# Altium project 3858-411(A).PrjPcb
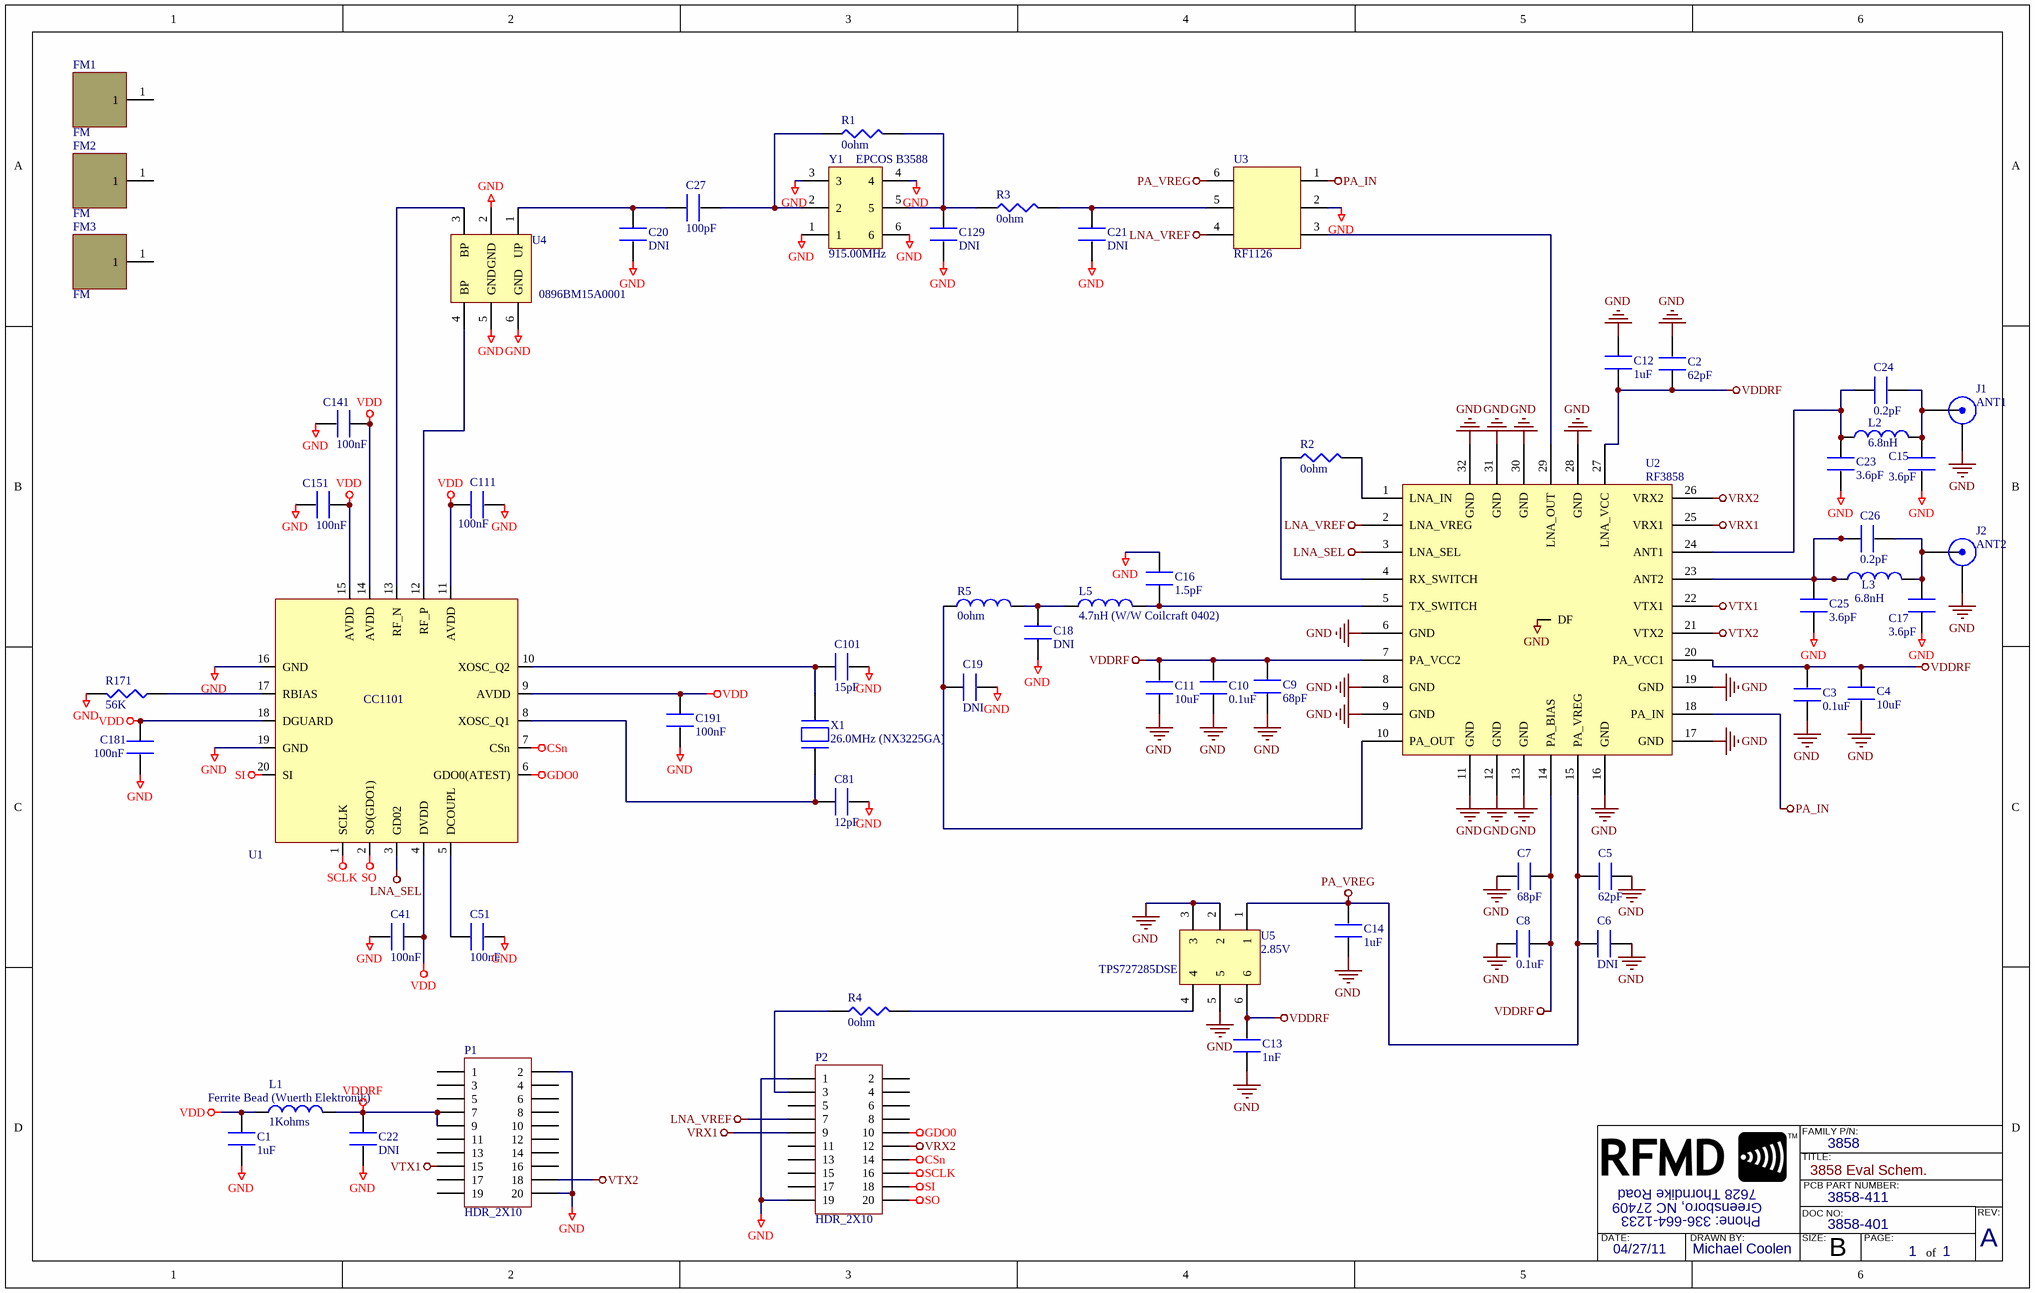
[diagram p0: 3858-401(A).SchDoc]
1 sheet, 62 parts. Net scope: global (net labels, ports and power ports of the same name join across sheets).
Board file: 3858-411(A).PcbDoc

## Sheet 3858-401(A).SchDoc: (this field not used)
size B; Organization: (this field not used); Address1: (this field not used); Address2: (this field not used); Address3: (this field not used); Address4: (this field not used); DocumentNumber: (this field not used); Revision: (this field not used); SheetNumber: (this field not used); SheetTotal: (this field not used); Date: (this field not used); ApprovedBy: (this field not used); CheckedBy: (this field not used); Author: (this field not used); CompanyName: (this field not used); DrawnBy: (this field not used); Engineer: (this field not used); AFamilypn: 3858; PageSetup: Record=PageOptions|CenterHorizontal=True|CenterVertical=True|PrintScale=1.12|XCorrection=1.00|YCorrection=1.00|PrintKind=2|BorderSize=5000000|LeftOffset=0|BottomOffset=0|Orientation=2|PaperLength=1000|PaperWidth=1000|Scale=100|PaperSource=7|PrintQuality=-4|MediaType=1|DitherType=10|PaperKind=11 x 17|PrintScaleMode=1; Apcbpartnumber: 3858-411; Atitle: 3858 Eval Schem.; Adocumentnumber: 3858-401; Apagenumber: 1; Apagenumbertotal: 1; Arevision: A; Adrawnby: Michael Coolen; Adate: 04/27/11

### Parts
C1  1uF  [0603(A)]
C2  62pF  [0402(A)]
C3  0.1uF  [0402(A)]
C4  10uF  [0603(A)]
C5  62pF  [0402(A)]
C6  DNI  [0402(A)]
C7  68pF  [0402(A)]
C8  0.1uF  [0402(A)]
C9  68pF  [0402(A)]
C10  0.1uF  [0402(A)]
C11  10uF  [0603(A)]
C12  1uF  [0402(A)]
C13  1nF  [0603(A)]
C14  1uF  [0603(A)]
C15  3.6pF  [0402_S]
C16  1.5pF  [0402_S]
C17  3.6pF  [0402_S]
C18  DNI  [0402_S]
C19  DNI  [0402_S]
C20  DNI  [0402_S]
C21  DNI  [0402_S]
C22  DNI  [0603(A)]
C23  3.6pF  [0402_S]
C24  0.2pF  [0402_S]
C25  3.6pF  [0402_S]
C26  0.2pF  [0402_S]
C27  100pF  [0402_S]
C41  100nF  [0402_TI]
C51  100nF  [0402_TI]
C81  12pF  [0402_TI]
C101  15pF  [0402_TI]
C111  100nF  [0402_TI]
C129  DNI  [0402_TI]
C141  100nF  [0402_TI]
C151  100nF  [0402_TI]
C181  100nF  [0402_TI]
C191  100nF  [0402_TI]
FM1  FM  [FM]
FM2  FM  [FM]
FM3  FM  [FM]
J1  ANT1  [SMA_008_MABDC_GP1_VIPER]
J2  ANT2  [SMA_008_MABDC_GP1_VIPER]
L1  1Kohms  [0603_S]
L2  6.8nH  [0402_S]
L3  6.8nH  [0402_S]
L5  4.7nH (W/W Coilcraft 0402)  [0402_S]
LOGO  RFMDLOGO  [RFMD_LOGO]  (value not drawn)
P1  HDR_2X10  [20PIN_CON]
P2  HDR_2X10  [20PIN_CON]
R1  0ohm  [0402_S]
R2  0ohm  [0402_S]
R3  0ohm  [0402_S]
R4  0ohm  [0402_S]
R5  0ohm  [0402_S]
R171  56K  [0402_TI]
U1  CC1101  [CC1101]
U2  RF3858  [RF3858B]
U3  RF1126  [1126]
U4  0896BM15A0001  [JOHANSON 896MHz]
U5  2.85V  [TPS727XX]
X1  26.0MHz (NX3225GA)  [Crystal]
Y1  915.00MHz  [Saw Epcos B3588]

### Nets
CSn: P2.14 U1.7(CSn)
GDO0: P2.10 U1.6(GDO0(ATEST))
GND: C1.2 C2.2 C3.1 C4.2 C5.1 C6.2 C7.2 C8.1 C9.2 C10.1 C11.1 C12.1 C13.1 C14.1 C15.2 C16.1 C17.2 C18.2 C19.2 C20.2 C21.2 C22.2 C23.2 C25.2 C41.2 C51.2 C81.2 C101.2 C111.2 C129.2 C141.2 C151.2 C181.2 C191.2 J1.2(GND) J1.3(GND) J1.4(GND) J1.5(GND) J1.6(GND) J1.7(GND) J1.8(GND) J1.9(GND) J2.2(GND) J2.3(GND) J2.4(GND) J2.5(GND) J2.6(GND) J2.7(GND) J2.8(GND) J2.9(GND) P1.2 P1.20 P2.1 P2.19 R171.2 U1.16(GND) U1.19(GND) U1.21(GND) U2.6(GND) U2.8(GND) U2.9(GND) U2.11(GND) U2.12(GND) U2.13(GND) U2.16(GND) U2.17(GND) U2.19(GND) U2.28(GND) U2.30(GND) U2.31(GND) U2.32(GND) U2.33(DF) U3.2 U3.7 U4.2(GND) U4.5(GND) U4.6(GND) U5.2 U5.3 U5.5 Y1.1 Y1.3 Y1.4 Y1.6
LNA_SEL: U1.3(GD02) U2.3(LNA_SEL)
LNA_VREF: P2.7 U2.2(LNA_VREG) U3.4
PA_IN: U2.18(PA_IN) U3.1
PA_VREG: C5.2 C6.1 C14.2 U2.15(PA_VREG) U3.6 U5.1
SCLK: P2.16 U1.1(SCLK)
SI: P2.18 U1.20(SI)
SO: P2.20 U1.2(SO(GDO1))
VDD: C1.1 C41.1 C111.1 C141.1 C151.1 C181.1 C191.1 L1.1 U1.4(DVDD) U1.9(AVDD) U1.11(AVDD) U1.14(AVDD) U1.15(AVDD) U1.18(DGUARD)
VDDRF: C2.1 C3.2 C4.1 C7.1 C8.2 C9.1 C10.2 C11.2 C12.2 C13.2 C22.1 L1.2 P1.7 P1.9 U2.7(PA_VCC2) U2.14(PA_BIAS) U2.20(PA_VCC1) U2.27(LNA_VCC) U5.6
VRX1: P2.9 U2.25(VRX1)
VRX2: P2.12 U2.26(VRX2)
VTX1: P1.15 U2.22(VTX1)
VTX2: P1.18 U2.21(VTX2)
NetC15_1: C15.1 C24.2 J1.1(I/O) L2.2
NetC16_2: C16.2 L5.2 U2.5(TX_SWITCH)
NetC17_1: C17.1 C26.2 J2.1(I/O) L3.2
NetC18_1: C18.1 L5.1 R5.2
NetC19_1: C19.1 R5.1 U2.10(PA_OUT)
NetC20_1: C20.1 C27.1 U4.1(UP)
NetC21_1: C21.1 R3.2 U3.5
NetC23_1: C23.1 C24.1 L2.1 U2.24(ANT1)
NetC25_1: C25.1 C26.1 L3.1 U2.23(ANT2)
NetC27_2: C27.2 R1.1 Y1.2
NetC51_1: C51.1 U1.5(DCOUPL)
NetC81_1: C81.1 U1.8(XOSC_Q1) X1.1
NetC101_1: C101.1 U1.10(XOSC_Q2) X1.2
NetC129_1: C129.1 R1.2 R3.1 Y1.5
NetP2_3: P2.3 R4.1
NetR2_1: R2.1 U2.4(RX_SWITCH)
NetR2_2: R2.2 U2.1(LNA_IN)
NetR4_2: R4.2 U5.4
NetR171_1: R171.1 U1.17(RBIAS)
NetU1_12: U1.12(RF_P) U4.4(BP)
NetU1_13: U1.13(RF_N) U4.3(BP)
NetU2_29: U2.29(LNA_OUT) U3.3

Not connected (* = marked no-connect by the designer): FM1 1; FM2 1; FM3 1; P1 1 3 4 5 6 8 10 11 12 13 14 16 17 19 NC(21); P2 2 4 5 6 8 11 13 15 17 NC(21)

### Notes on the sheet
- (near U5) TPS727285DSE
- (near L1) Ferrite Bead (Wuerth Elektronik)

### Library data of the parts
C1-C27 C41 C51 C81 C101 C111 C129 C141 C151 C181 C191 = CAPACITOR(A): Capacitor
J1 J2 = SMA_008: SMA Connector
L1-L3 L5 R5 = INDUCTOR(A): Inductor
LOGO = RFMDLOGO: RFMD LOGO
R1-R4 R171 = RESISTOR(A): Resistor
U1 = PKG_20L
U3 = PKG_6L
U4 = BALUN JOHANSON
U5 Y1 = SAW 6L: SAW FILTER
X1 = CRYSTAL(A): CRYSTAL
